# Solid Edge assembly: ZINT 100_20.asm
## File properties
Title: Zylinder
Author: bmolnar
Template: iso metric assembly.asm
Last saved by: bmolnar
Revision: 15
Application: Solid Edge
Username: bmolnar
Dokumentum tartalom típus: 1
Document Number: ZINT 100/20
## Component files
hrungsstange.par
Profilrohr.par
Platte.par
Kolbenstange.par
Kit_2.par
Kit_1.par
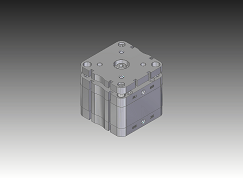
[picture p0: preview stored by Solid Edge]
